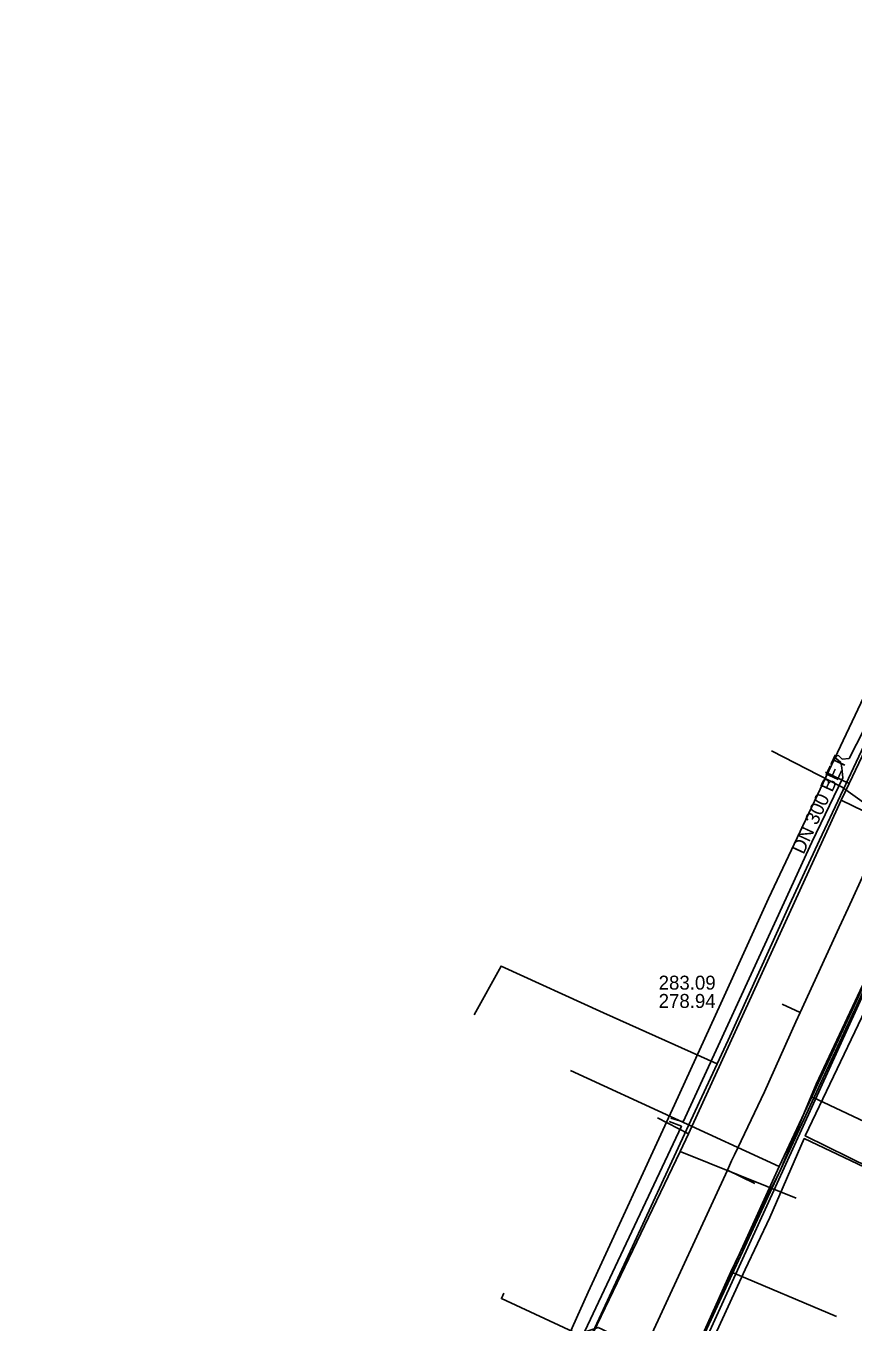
# Model space of a CAD drawing. Extents: x -600309 to -598967, y -1161267 to -1160292.
# Drawn here: x -600119.2 to -600071.8, y -1160426.8 to -1160352.5 of the extents above; entities that cross this region are included whole.
import ezdxf

# ---------------------------------------------------------------- set-up
doc = ezdxf.new("R2010")
doc.units = 0
for name, color, linetype in [('Vrstva 12', 7, 'Continuous'), ('Vrstva 13', 7, 'Continuous'), ('Vrstva 19', 7, 'Continuous'), ('Vrstva 42', 7, 'Continuous'), ('Vrstva 55', 7, 'Continuous'), ('Vrstva 58', 7, 'Continuous'), ('Vrstva 9', 7, 'Continuous')]:
    doc.layers.add(name, color=color, linetype=linetype)

msp = doc.modelspace()

# ---------------------------------------------------------------- linework, layer by layer
at = {"layer": 'Vrstva 12'}
for points in [[(-600053.81, -1160360.62), (-600063.99, -1160379.24), (-600070.07, -1160391.48), (-600073.68, -1160399.16), (-600075.4, -1160402.88), (-600078.93, -1160410.64)], [(-600078.78, -1160423.93), (-600077.24, -1160420.74), (-600075.91, -1160418.03), (-600073.87, -1160413.15), (-600069.86, -1160404.61), (-600068.79, -1160402.35), (-600068.63, -1160401.75), (-600068.27, -1160401.34), (-600066.13, -1160396.83)], [(-600079.56, -1160411.99), (-600086.09, -1160409.06), (-600091.96, -1160406.39), (-600093.51, -1160409.18)], [(-600078.93, -1160410.64), (-600079.56, -1160411.99)], [(-600079.56, -1160411.99), (-600081.32, -1160415.78)], [(-600081.32, -1160415.78), (-600086.7, -1160427.39), (-600089.44, -1160433.33), (-600093.17, -1160441.4)], [(-600083.05, -1160433.26), (-600082.47, -1160432.14), (-600078.78, -1160423.93)], [(-600078.78, -1160423.93), (-600072.7, -1160426.48)]]:
    msp.add_lwpolyline(points, dxfattribs=at)
at = {"layer": 'Vrstva 13'}
for p, q in [((-600075.988, -1160417.875), (-600087.972, -1160412.366)), ((-600074.114, -1160413.884), (-600061.984, -1160419.647))]:
    msp.add_line(p, q, dxfattribs=at)
for points in [[(-600043.34, -1160353.45), (-600045.144, -1160355.652), (-600059.499, -1160382.793), (-600064.92, -1160394.071), (-600067.208, -1160399.064), (-600067.79, -1160400.261), (-600068.48, -1160401.76), (-600074.114, -1160413.884), (-600075.988, -1160417.875), (-600082.537, -1160432.282), (-600086.839, -1160441.714), (-600093.399, -1160455.743), (-600098.87, -1160467.43), (-600100.834, -1160472.035), (-600101.904, -1160474.347), (-600111.307, -1160494.031), (-600112.353, -1160496.209), (-600121.987, -1160516.186), (-600122.188, -1160516.468)], [(-600081.34, -1160429.68), (-600080.15, -1160427.2), (-600071.2, -1160407.88), (-600062.68, -1160389.74), (-600049.97, -1160365.66)], [(-600081.34, -1160429.68), (-600086.18, -1160427.21), (-600086.38, -1160427.11), (-600087.54, -1160427.5), (-600091.94, -1160425.46), (-600091.8, -1160425.15)]]:
    msp.add_lwpolyline(points, dxfattribs=at)
at = {"layer": 'Vrstva 19'}
for points in [[(-600051.432, -1160356.995), (-600051.67, -1160357.47), (-600052.24, -1160358.5), (-600053.875, -1160361.413), (-600054.44, -1160362.42), (-600057.61, -1160367.59), (-600060.27, -1160372.46), (-600066.42, -1160384.21), (-600071.987, -1160395.908), (-600072.44, -1160396.86), (-600081.21, -1160416.01), (-600081.68, -1160417.02), (-600087.34, -1160428.81), (-600093.67, -1160442.82), (-600097.21, -1160450.62), (-600102.72, -1160462.51), (-600107.62, -1160472.9), (-600115.47, -1160490.04), (-600118.4, -1160496.38), (-600123.238, -1160507.012)], [(-600071.987, -1160395.908), (-600073.33, -1160395.26)], [(-600072.44, -1160396.86), (-600065.98, -1160400)], [(-600081.21, -1160416.01), (-600082.99, -1160415.09)], [(-600081.68, -1160417.02), (-600075.03, -1160419.69)]]:
    msp.add_lwpolyline(points, dxfattribs=at)
at = {"layer": 'Vrstva 42'}
for points in [[(-600070.71, -1160392.02), (-600071.98, -1160394.47), (-600072.374, -1160394.523), (-600072.599, -1160394.307), (-600072.73, -1160394.319)], [(-600072.73, -1160394.319), (-600072.737, -1160394.451), (-600072.464, -1160394.713), (-600072.4, -1160395.02), (-600072.345, -1160395.584), (-600074.127, -1160399.273), (-600075.712, -1160402.734), (-600081.512, -1160415.317), (-600082.209, -1160415.104)], [(-600088.96, -1160448.5), (-600089.32, -1160448.04), (-600088.902, -1160447.783), (-600085.419, -1160440.033), (-600082.172, -1160432.872), (-600076.668, -1160435.337), (-600076.981, -1160436.018), (-600076.705, -1160436.14), (-600076.135, -1160435.136), (-600081.958, -1160432.528), (-600077.956, -1160423.786), (-600076.536, -1160420.801), (-600074.553, -1160416.276), (-600069.561, -1160418.649), (-600069.528, -1160418.577), (-600074.501, -1160416.126), (-600071.256, -1160409.31), (-600070.05, -1160406.516), (-600066.079, -1160398.205), (-600064.587, -1160398.779), (-600064.735, -1160399.059), (-600065.15, -1160398.935), (-600065.322, -1160399.45)], [(-600082.302, -1160415.3), (-600081.608, -1160415.574), (-600087.151, -1160427.322), (-600088.336, -1160429.951), (-600088.629, -1160430.634), (-600089.789, -1160433.162), (-600092.7, -1160439.431), (-600094.007, -1160438.61), (-600093.973, -1160438.354), (-600093.723, -1160438.376), (-600093.52, -1160437.957)]]:
    msp.add_lwpolyline(points, dxfattribs=at)
at = {"layer": 'Vrstva 55'}
msp.add_lwpolyline([(-600052.28, -1160370.18), (-600052.64, -1160370.62), (-600062.46, -1160389.3), (-600070.54, -1160406.63), (-600084.85, -1160438), (-600100.93, -1160472.64), (-600115.08, -1160503.1)], dxfattribs=at)
at = {"layer": 'Vrstva 58'}
msp.add_lwpolyline([(-600061.36, -1160351.94), (-600057.83, -1160355), (-600054.28, -1160357.9), (-600054.07, -1160358.38), (-600054.2, -1160358.96), (-600054.67, -1160359.76), (-600057.41, -1160364.5), (-600060.27, -1160369.6), (-600062.43, -1160373.6), (-600064.33, -1160377.23), (-600066.8, -1160382), (-600069.46, -1160387.38), (-600072.83, -1160394.5), (-600076.61, -1160402.5), (-600079.34, -1160408.54), (-600082.01, -1160414.34), (-600086.97, -1160425.09), (-600090.81, -1160433.66)], dxfattribs=at)
at = {"layer": 'Vrstva 9'}
for p, q in [((-600075.829, -1160408.569), (-600074.799, -1160409.045)), ((-600077.388, -1160418.854), (-600078.969, -1160418.088))]:
    msp.add_line(p, q, dxfattribs=at)
for points in [[(-600060.809, -1160378.743), (-600062.732, -1160382.887), (-600062.948, -1160383.354), (-600065.231, -1160388.304), (-600065.742, -1160389.412), (-600066.726, -1160391.544), (-600068.104, -1160394.532), (-600069.676, -1160397.938), (-600071.021, -1160400.854), (-600072.038, -1160403.058), (-600072.549, -1160404.166), (-600074.799, -1160409.045), (-600075.045, -1160409.578), (-600076.842, -1160413.602)], [(-600070.874, -1160397.223), (-600071.027, -1160397.1), (-600072.372, -1160396.12), (-600076.439, -1160394.03)], [(-600076.842, -1160413.602), (-600078.568, -1160417.216), (-600078.727, -1160417.561), (-600078.969, -1160418.088), (-600083.412, -1160427.727)]]:
    msp.add_lwpolyline(points, dxfattribs=at)

# ---------------------------------------------------------------- texts
at = {"layer": 'Vrstva 12'}
msp.add_text('DN 300 BET', height=0.8, rotation=65.25989, dxfattribs=at).set_placement((-600074.599, -1160400.021))
for s, p in [('283.09', (-600082.915, -1160407.736)), ('278.94', (-600082.915, -1160408.786))]:
    msp.add_text(s, height=0.8, dxfattribs=at).set_placement(p)

doc.saveas('drawing.dxf')
